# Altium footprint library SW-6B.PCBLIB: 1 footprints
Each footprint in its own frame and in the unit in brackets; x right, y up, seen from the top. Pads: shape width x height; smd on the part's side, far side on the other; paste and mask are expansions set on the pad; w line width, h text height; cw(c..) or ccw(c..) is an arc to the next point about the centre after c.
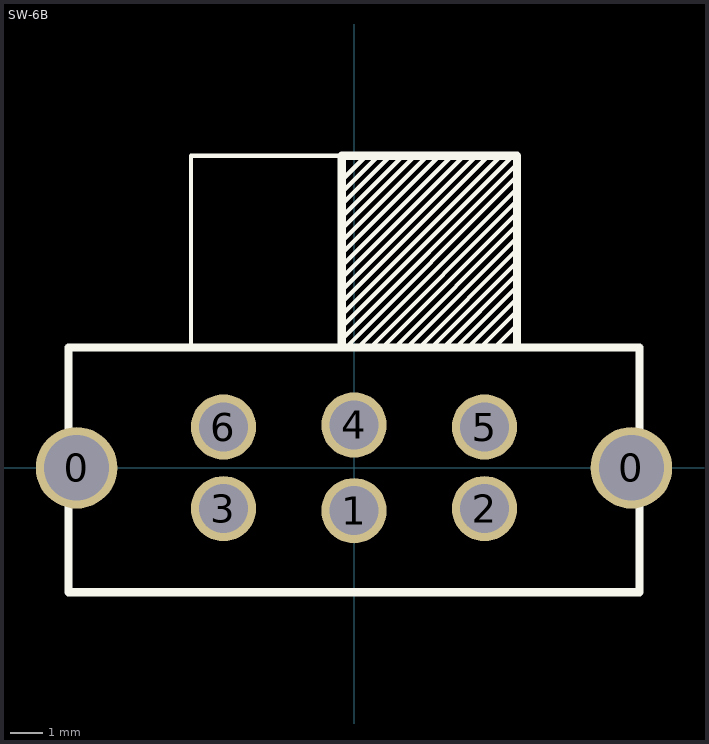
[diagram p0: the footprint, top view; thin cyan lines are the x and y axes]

## SW-6B [mil]
pads (8):
  round 100 hole 80: 0(-340,0) 0(340,0)
  round 80 hole 60: 1(0,-52.5) 2(160,-50) 3(-160,-50) 4(0,52.5) 5(160,50) 6(-160,50)
Top Overlay:
  lines w5: -200,147.5 -200,382.5 -15,382.5 ; -15,157.5 200,372.5 ; -15,172.5 195,382.5 ; -15,187.5 180,382.5 ; -15,202.5 165,382.5 ; -15,217.5 150,382.5 ; -15,232.5 135,382.5 ; -15,247.5 120,382.5 ; -15,262.5 105,382.5 ; -15,277.5 90,382.5 ; -15,292.5 75,382.5 ; -15,307.5 60,382.5 ; -15,322.5 45,382.5 ; -15,330 -15,337.5 30,382.5 ; -15,350 -15,352.5 15,382.5 ; -10,147.5 200,357.5 200,382.5 200,297.5 50,147.5 ; 5,147.5 200,342.5 ; 65,147.5 200,282.5 ; 80,147.5 200,267.5 200,310 ; 95,147.5 200,252.5 ; 110,147.5 200,237.5 ; 125,147.5 200,222.5 ; 140,147.5 200,207.5 ; 155,147.5 200,192.5 ; 165,147.5 172.5,147.5 200,175 ; 200,312.5 35,147.5 20,147.5 200,327.5 200,355
  lines w10: -15,147.5 -15,382.5 200,382.5 200,147.5 ; -350,-152.5 350,-152.5 350,-2.5 350,147.5 -350,147.5 -350,-2.5 -350,-152.5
